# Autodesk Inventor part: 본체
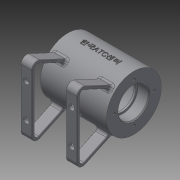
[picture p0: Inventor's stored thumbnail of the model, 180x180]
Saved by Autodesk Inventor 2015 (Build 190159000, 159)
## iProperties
Created: 2021-12
Part Number: 본체
Material: 일반
Document SubType Name: Modeling
Designer: pc-04
Density: 1 g/cm^3
Appearance: 기본값
Author: pc-04
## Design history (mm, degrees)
sketch "스케치1"
  geometry: L1 (-71.853, 0)-(122.253, 0); L2 (-35, 71)-(-35, 84); L3 (-35, 84)-(35, 84); L4 (35, 84)-(35, 71); L5 (35, 71)-(23, 71); L6 (23, 71)-(23, 69); L7 (23, 69)-(21, 69); L8 (21, 69)-(21, 76); L9 (21, 76)-(-21, 76); L10 (-21, 76)-(-21, 69); L11 (-21, 69)-(-23, 69); L12 (-23, 69)-(-23, 71); L13 (-23, 71)-(-35, 71); L14 (0, 0)-(0, 157.846); L15 (-71.853, 55)-(77.25, 55)
  constraints: 30 end point, 10 perpendicular, 3 point on line, 2 horizontal, 2 vertical, 1 collinear, 3 other
  dimensions: "d0" = 55 distance from line of L1 L15.end; "d1" = 28 diameter of L7 L15; "d2" = 32 diameter of L5 L15; "d3" = 58 diameter of L3 L15; "d4" = 42 diameter of L9 L15; "d5" = 42 distance of L8.end L9.end; "d6" = 70 distance of L2.end L3.end; "d7" = 12 distance of L4.end L5.end
revolve "회전1" sketch "스케치1" stored, may be unused: angle "d8" = 90 deg
node "작업 평면2"
  node "작업 평면1"
sketch "스케치2"
  geometry: C1 r 5 at (0, 0); 1 further point
  constraints: 1 centre point, 1 coincident
  dimensions: "d11" = 10 diameter of C1
extrude "돌출1" join sketch "스케치2" stored distance "d12" = 10; taper "d13" = 0 deg
sketch "스케치3"
  geometry: L1 (55, 0)-(24.93, -10.945); L2 (55, 52.445)-(55, -65.406); 1 further point
  constraints: 4 end point, 1 horizontal alignment, 1 point on line, 1 vertical
  dimensions: "d14" = 55 distance of point (0, 0) L1.start; "d15" = 70 deg angle of L1 L2; "d16" = 32 distance of L1.start L1.end
node "작업 평면3"
sketch "스케치4"
  geometry: C1 r 6 at (0, 0); 2 further points
  constraints: 1 centre point, 1 coincident
  dimensions: "d17" = 12 diameter of C1
extrude "돌출2" join sketch "스케치4" stored distance "d18" = 10; taper "d19" = 0 deg
node "작업 평면4"
sketch "스케치5"
  geometry: L1 (0, 40)-(0, -40); L2 (0, -40)-(39.614, -21.528); L3 (0, 40)-(39.614, 21.528); L4 (0, 0)-(65.899, 0); L5 (38.346, 18.809)-(3, 35.291); L6 (3, 35.291)-(3, -35.291); L7 (3, -35.291)-(38.346, -18.809); L8 (39.614, -21.528)-(38.346, -18.809); L9 (39.614, 21.528)-(38.346, 18.809); 1 further point
  constraints: 18 end point, 2 equal length, 1 coincident, 1 horizontal, 1 midpoint, 1 perpendicular, 1 vertical, 3 other
  dimensions: "d21" = 65 deg angle of L1 L2; "d22" = 80 distance of L1.start L1.end; "d23" = 3 distance between parallel lines of L3 L5; "d24" = 39 distance from line of L5.end L9
extrude "돌출3" join sketch "스케치5" stored distance "d25" = 12; taper "d26" = 0 deg
sketch "스케치6"
  geometry: L1 (0, 75.291)-(12, 75.291) reference; L2 (6, 75.291)-(6, -4.709); L3 (12, -4.709)-(0, -4.709) reference; L4 (6, 35.291)-(20.254, 35.291); 3 further points
  constraints: 4 end point, 3 midpoint, 2 point on line, 1 horizontal, 1 symmetric about line
  dimensions: "d27" = 36 distance of point (6, 17.291) point (6, 53.291)
hole "구멍1" sketch "스케치6" at (6, 53.291), (6, 17.291) diameter "d28" = 6; stored, may be unused: countersink angle "d32" = 90 deg, drill point angle "d34" = 118 deg; dims "d29" = 6, "d30" = 4, "d31" = 2, "d33" = 8
fillet "모깎기1" dims "d35" = 6, "d36" = 3
fillet "모깎기2" dims "d37" = 0.5
fillet "모깎기3" dims "d38" = 3
sketch "스케치7"
  geometry: A1 r 21 centre (0, 0) between (0, 21) and (21, 0); 3 further points
  constraints: 4 point on circle, 3 vertical alignment, 2 horizontal alignment, 1 centre point
  dimensions: "d39" = 42 diameter of A1; "d40" = 55 distance of point (0, -55) A1.centre
hole "구멍2" sketch "스케치7" at (0, 21), (21, 0), (0, -21), (-21, 0) diameter "d41" = 3.242; stored, may be unused: countersink angle "d45" = 90 deg, drill point angle "d47" = 118 deg; dims "d42" = 8, "d43" = 4, "d44" = 2, "d46" = 10
hole "구멍3" diameter "d50" = 5.188; stored, may be unused: countersink angle "d54" = 90 deg, drill point angle "d56" = 118 deg; dims "d48" = 10, "d49" = 10, "d51" = 12, "d52" = 4, "d53" = 2, "d55" = 25
hole "구멍4" diameter "d59" = 5.188; stored, may be unused: countersink angle "d63" = 90 deg, drill point angle "d65" = 118 deg; dims "d57" = 10, "d58" = 10, "d60" = 6, "d61" = 4, "d62" = 2, "d64" = 8
hole "구멍5" diameter "d68" = 3; stored, may be unused: countersink angle "d72" = 90 deg, drill point angle "d74" = 118 deg; dims "d66" = 10, "d67" = 10, "d69" = 6, "d70" = 4, "d71" = 2, "d73" = 25
fillet "모깎기4" dims "d75" = 1
fillet "모깎기5" dims "d76" = 0.3, "d77" = 3
chamfer "모따기1" distance "d78" = 1; stored, may be unused: second distance "d79" = 2, angle "d80" = 45 deg
sketch "스케치8"
  geometry: L1 (-26.869, 64.232)-(26.869, 64.232); L2 (26.869, 64.232)-(26.869, 45.768); L3 (26.869, 45.768)-(-26.869, 45.768); L4 (-26.869, 45.768)-(-26.869, 64.232); L5 (-26.869, 64.232)-(26.869, 64.232); L6 (26.869, 64.232)-(26.869, 45.768); L7 (26.869, 45.768)-(-26.869, 45.768); L8 (-26.869, 45.768)-(-26.869, 64.232); L9 (26.869, 64.232)-(-26.869, 45.768); 2 further points
  constraints: 10 end point, 2 coincident, 2 parallel, 1 horizontal, 1 midpoint, 1 perpendicular, 1 vertical alignment, 2 other
  dimensions: "d81" = 55 distance of point (0, 0) point (0, 55)
sketch "스케치9"
  geometry: A1 r 29.5 centre (55, 0) between (84.5, 0) and (25.5, 0); 1 further point
  constraints: 2 point on circle, 1 centre point, 1 horizontal alignment
  dimensions: "d82" = 55 distance of point (0, 0) A1.centre; "d83" = 59 diameter of A1
feature "돌출 곡면1" sketch "스케치9" dims "d84" = 45, "d85" = 0
extrude "돌출4" join sketch "스케치8" stored distance "d86" = 45; taper "d87" = 0 deg
node "솔리드1"
mirror "대칭1"
mirror "대칭2"
node "곡면1"
other parameters: "d9" = 55, "d10" = 32, "d20" = 24
